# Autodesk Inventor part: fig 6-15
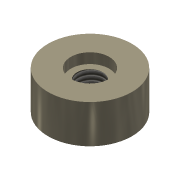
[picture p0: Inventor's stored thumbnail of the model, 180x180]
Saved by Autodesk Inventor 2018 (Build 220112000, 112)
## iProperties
Shininess: 65.0
Angle Display Precision: 2
Document Length Units: 11269
Document Angle Units: 11279
Document Time Units: 11290
Document Mass Units: 11283
Document Length Units Precision: 3
Document Angle Units Precision: 2
Created: 2001-11
Part Number: fig 6-15
Document SubType Name: Modeling
Designer: Renu Muthoo
Density: 1 g/cm^3
Material: Generic
Appearance: Metal-Titanium (Polished)
Density: 0.0
Volumn: 0.0
Area: 0.0
PropertySet Name: Model Information
Control State: 0
Master: False
Checked Out: False
Author: Renu Muthoo
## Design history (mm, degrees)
sketch "Sketch1"
  geometry: C1 r 16.401 at (0, 0)
  constraints: 1 centre point
extrude "Extrusion1" new body sketch "Sketch1" distance "d0" = 15; taper "d1" = 0 deg
hole "Hole3" diameter "d18" = 10.106; stored, may be unused: countersink angle "d22" = 90 deg, drill point angle "d24" = 118 deg; dims "d16" = 10, "d17" = 10, "d19" = 6, "d20" = 15, "d21" = 4, "d23" = 10
body "Solid1"
